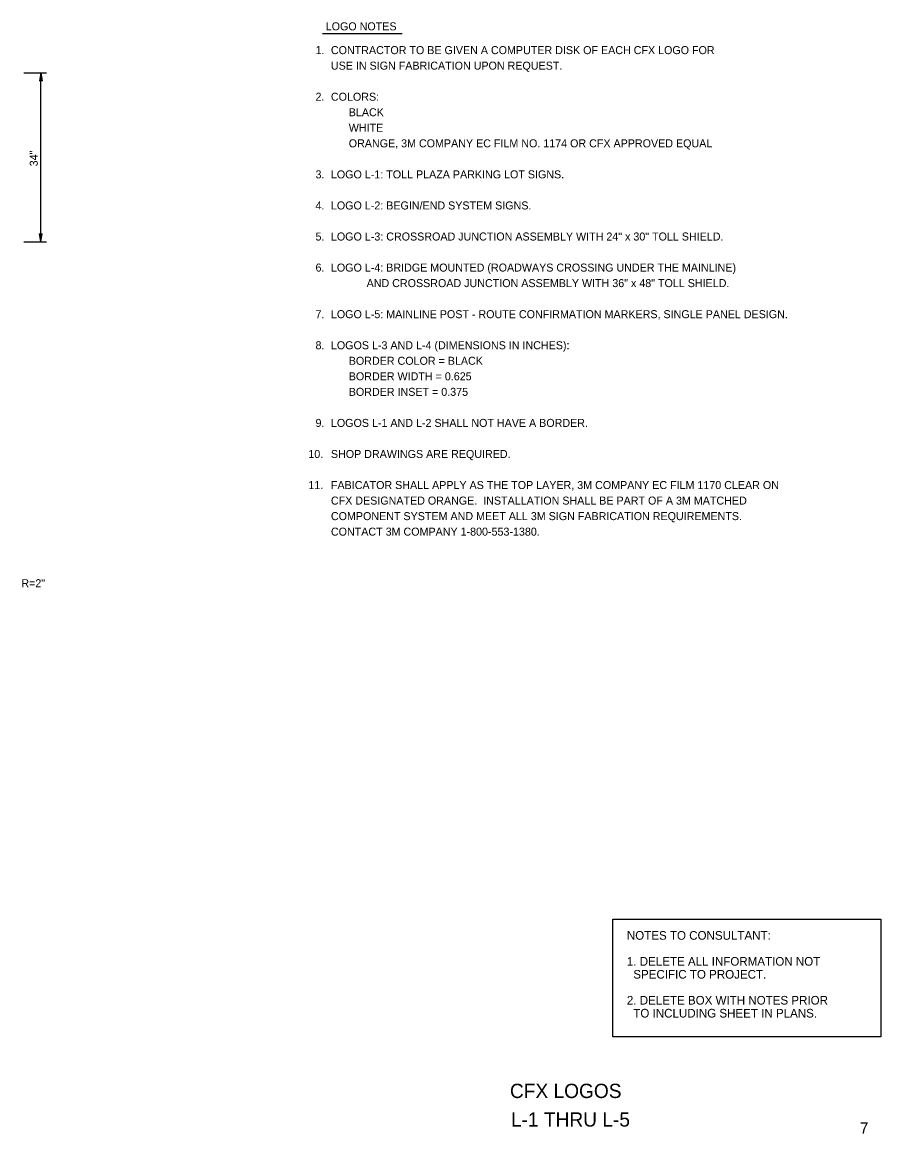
# Model space of a CAD drawing. Extents: x 60714 to 61343, y 7599 to 7998.
# Drawn here: x 61043.1 to 61343.3, y 7609.2 to 7998 of the extents above; entities that cross this region are included whole.
import ezdxf

# ---------------------------------------------------------------- set-up
doc = ezdxf.new("R2010")
doc.units = 0
for name, color, linetype in [('2', 7, 'Continuous'), ('21', 7, 'Continuous'), ('TextAlert', 7, 'Continuous'), ('TextMisc', 7, 'Continuous'), ('TextShtNo', 7, 'Continuous')]:
    doc.layers.add(name, color=color, linetype=linetype)

msp = doc.modelspace()

# ---------------------------------------------------------------- linework, layer by layer
at = {"layer": '2'}
for p, q in [((61148.08, 7993.97), (61175.94, 7993.97)), ((61043.58, 7980.26), (61051.58, 7980.26)), ((61049.58, 7921.12), (61049.58, 7980.26)), ((61043.58, 7921.12), (61051.58, 7921.12))]:
    msp.add_line(p, q, dxfattribs=at)
at = {"layer": '21'}
for p, q in [((61049.58, 7980.26), (61049.09, 7977.49)), ((61049.58, 7980.26), (61049.35, 7977.6)), ((61049.58, 7980.26), (61050.07, 7977.49)), ((61049.58, 7980.26), (61049.81, 7977.6)), ((61049.09, 7977.49), (61049.58, 7977.7)), ((61049.58, 7977.7), (61050.07, 7977.49)), ((61049.58, 7921.12), (61049.09, 7923.89)), ((61049.58, 7923.68), (61049.09, 7923.89)), ((61049.58, 7921.12), (61049.35, 7923.77)), ((61049.58, 7921.12), (61050.07, 7923.89)), ((61050.07, 7923.89), (61049.58, 7923.68)), ((61049.58, 7921.12), (61049.81, 7923.78))]:
    msp.add_line(p, q, dxfattribs=at)
at = {"layer": 'TextAlert'}
msp.add_lwpolyline([(61249.54, 7684.21), (61343.29, 7684.21), (61343.29, 7643.04), (61249.54, 7643.04)], close=True, dxfattribs=at)

# ---------------------------------------------------------------- texts
at = {"layer": '2'}
for s, p in [('LOGO NOTES', (61149.2, 7995.12)), ('R=2"', (61042.76, 7800.35))]:
    msp.add_text(s, height=2.8, dxfattribs=at).set_placement(p)
msp.add_text('34"', height=2.8, rotation=90, dxfattribs=at).set_placement((61048.49, 7947.55))
at = {"layer": '21'}
for s, p in [('1.', (61145.63, 7986.8)), ('CONTRACTOR TO BE GIVEN A COMPUTER DISK OF EACH CFX LOGO FOR', (61151.01, 7986.8)), ('USE IN SIGN FABRICATION UPON REQUEST.', (61151.01, 7981.37)), ('2.', (61145.63, 7970.5)), ('COLORS:', (61151.01, 7970.5)), ('      BLACK', (61151.01, 7965.07)), ('      WHITE', (61151.01, 7959.64)), ('      ORANGE, 3M COMPANY EC FILM NO. 1174 OR CFX APPROVED EQUAL', (61151.01, 7954.2)), ('3.', (61145.63, 7943.34)), ('LOGO L-1: TOLL PLAZA PARKING LOT SIGNS.', (61151.01, 7943.34)), ('4.', (61145.63, 7932.47)), ('LOGO L-2: BEGIN/END SYSTEM SIGNS.', (61151.01, 7932.47)), ('5.', (61145.63, 7921.6)), ('LOGO L-3: CROSSROAD JUNCTION ASSEMBLY WITH 24" x 30" TOLL SHIELD.', (61151.01, 7921.61)), ('6.', (61145.63, 7910.74)), ('LOGO L-4: BRIDGE MOUNTED (ROADWAYS CROSSING UNDER THE MAINLINE)', (61151.01, 7910.74)), ('            AND CROSSROAD JUNCTION ASSEMBLY WITH 36" x 48" TOLL SHIELD.', (61151.01, 7905.31)), ('7.', (61145.63, 7894.44)), ('LOGO L-5: MAINLINE POST - ROUTE CONFIRMATION MARKERS, SINGLE PANEL DESIGN.', (61151.01, 7894.44)), ('8.', (61145.63, 7883.57)), ('LOGOS L-3 AND L-4 (DIMENSIONS IN INCHES):', (61151.01, 7883.57)), ('      BORDER COLOR = BLACK', (61151.01, 7878.14)), ('      BORDER WIDTH = 0.625', (61151.01, 7872.71)), ('      BORDER INSET = 0.375', (61151.01, 7867.28)), ('9. ', (61145.63, 7856.41)), ('LOGOS L-1 AND L-2 SHALL NOT HAVE A BORDER.', (61151.01, 7856.41)), ('10.', (61143.12, 7845.54)), ('SHOP DRAWINGS ARE REQUIRED.', (61151.01, 7845.54)), ('11.', (61143.12, 7834.68)), ('FABICATOR SHALL APPLY AS THE TOP LAYER, 3M COMPANY EC FILM 1170 CLEAR ON ', (61151.01, 7834.68)), ('CFX DESIGNATED ORANGE.  INSTALLATION SHALL BE PART OF A 3M MATCHED ', (61151.01, 7829.24)), ('COMPONENT SYSTEM AND MEET ALL 3M SIGN FABRICATION REQUIREMENTS.  ', (61151.01, 7823.81)), ('CONTACT 3M COMPANY 1-800-553-1380.', (61151.01, 7818.38))]:
    msp.add_text(s, height=2.8, dxfattribs=at).set_placement(p)
at = {"layer": 'TextAlert'}
for s, p in [('NOTES TO CONSULTANT:', (61254.51, 7677.04)), ('1. DELETE ALL INFORMATION NOT', (61254.51, 7667.97)), ('  SPECIFIC TO PROJECT.', (61254.51, 7663.44)), ('2. DELETE BOX WITH NOTES PRIOR', (61254.51, 7654.36)), ('  TO INCLUDING SHEET IN PLANS.', (61254.51, 7649.83))]:
    msp.add_text(s, height=3.024, dxfattribs=at).set_placement(p)
at = {"layer": 'TextMisc'}
for s, p in [('       CFX LOGOS        ', (61200.62, 7621.67)), ('      L-1 THRU L-5      ', (61202.83, 7611.67))]:
    msp.add_text(s, height=5, rotation=360, dxfattribs=at).set_placement(p)
at = {"layer": 'TextShtNo'}
msp.add_text('7', height=4, rotation=360, dxfattribs=at).set_placement((61336, 7609.17))

doc.saveas('drawing.dxf')
